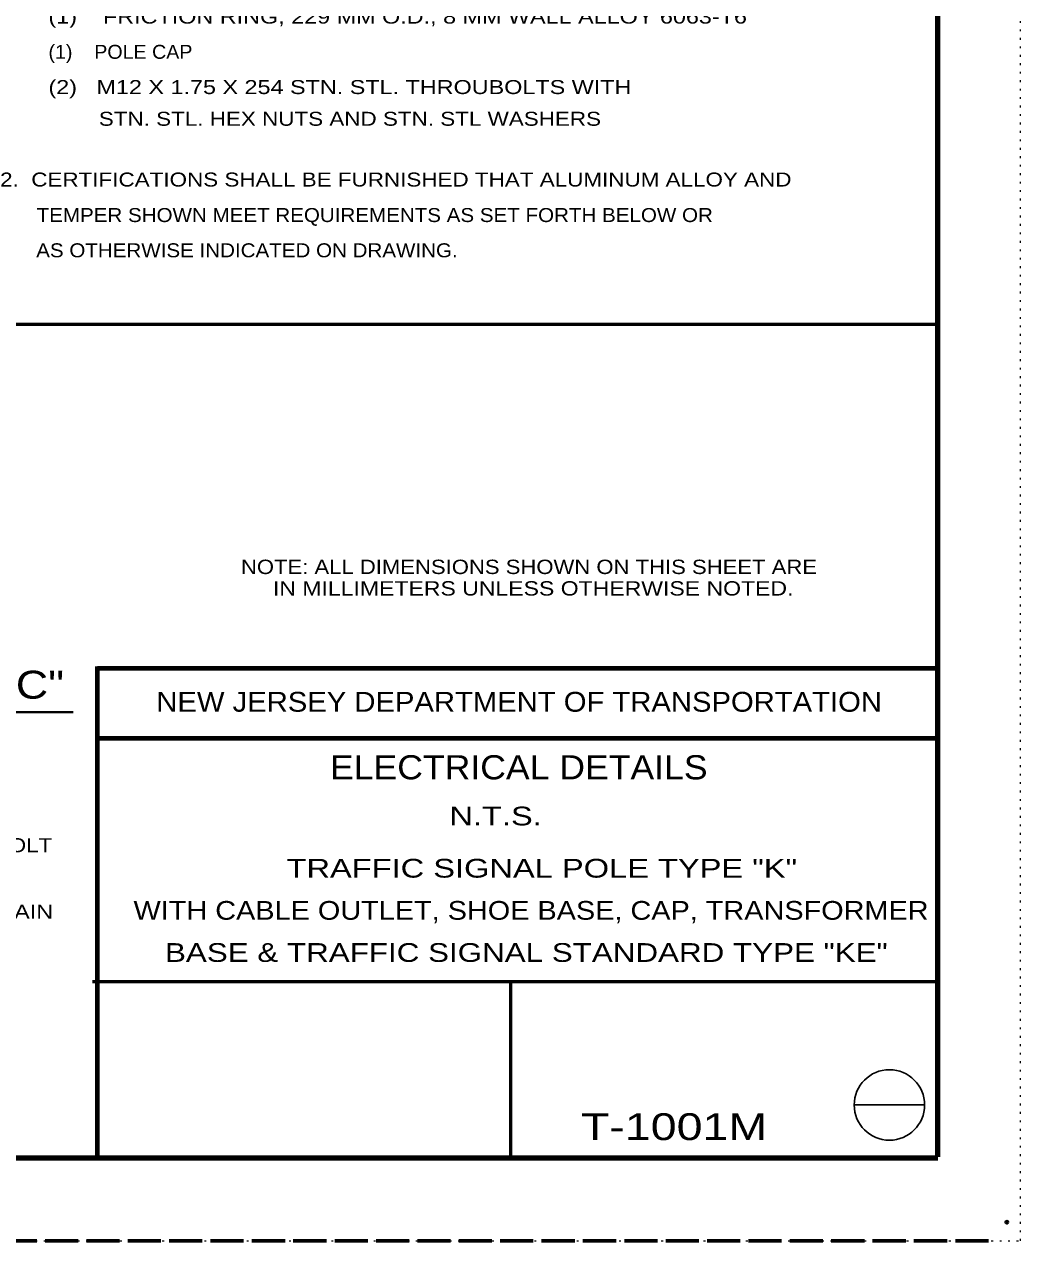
# Model space of a CAD drawing. Extents: x 312583 to 312854, y 144419 to 144597.
# Drawn here: x 312799.3 to 312853.5, y 144418.6 to 144484.7 of the extents above; entities that cross this region are included whole.
import ezdxf
from ezdxf.enums import TextEntityAlignment as Align

# ---------------------------------------------------------------- set-up
doc = ezdxf.new("R2010")
doc.units = 0
doc.header["$LTSCALE"] = 0.3
doc.header["$PDMODE"] = 32
doc.header["$PDSIZE"] = 0.15
doc.linetypes.add('DOTTED', pattern=[1.5, 0.3, -1.2])
doc.linetypes.add('LONG_DASHED', pattern=[7.5, 6, -1.5])
for name, color, linetype, lineweight in [('1', 7, 'Continuous', 40), ('10', 7, 'Continuous', 25), ('2', 7, 'Continuous', 13), ('62', 7, 'DOTTED', 13), ('63', 7, 'LONG_DASHED', 60)]:
    doc.layers.add(name, color=color, linetype=linetype, lineweight=lineweight)
doc.layers.add('5', color=7, linetype='Continuous')

msp = doc.modelspace()

# ---------------------------------------------------------------- linework, layer by layer
at = {"layer": '1', "lineweight": 158}
for p, q in [((312849, 144423.1446), (312849, 144585.0846)), ((312616.5, 144423.0846), (312849, 144423.0846))]:
    msp.add_line(p, q, dxfattribs=at)
at = {"layer": '1', "lineweight": 80}
for p, q in [((312803.31, 144423.1446), (312803.31, 144449.8146)), ((312803.31, 144449.7246), (312849, 144449.7246)), ((312803.31, 144445.9146), (312849, 144445.9146))]:
    msp.add_line(p, q, dxfattribs=at)
at = {"layer": '1', "lineweight": 53}
for p, q in [((312849, 144432.6666), (312803.0384, 144432.6666)), ((312825.7547, 144432.6666), (312825.7547, 144423.1446))]:
    msp.add_line(p, q, dxfattribs=at)
msp.add_lwpolyline([(312849, 144468.4167), (312795.5728, 144468.4167), (312795.5728, 144585.0846)], dxfattribs=at)
at = {"layer": '1'}
msp.add_point((312852.75, 144419.5846), dxfattribs=at)
at = {"layer": '10'}
msp.add_line((312844.4384, 144425.9659), (312848.2794, 144425.9659), dxfattribs=at)
msp.add_circle((312846.3635, 144425.9659), 1.9159, dxfattribs=at)
at = {"layer": '2', "lineweight": 40}
msp.add_line((312783.1061, 144447.3258), (312801.9889, 144447.3258), dxfattribs=at)
at = {"layer": '62'}
msp.add_lwpolyline([(312601.2, 144418.5846), (312853.5, 144418.5846), (312853.5, 144596.7846)], dxfattribs=at)
at = {"layer": '63'}
msp.add_line((312851.75, 144418.5846), (312583.526, 144418.5846), dxfattribs=at)

# ---------------------------------------------------------------- texts
at = {"layer": '1'}
for s, width, p in [('NOTE: ALL DIMENSIONS SHOWN ON THIS SHEET ARE', 1.15, (312811.1026, 144454.8446)), ('     IN MILLIMETERS UNLESS OTHERWISE NOTED.', 1.2, (312811.1025, 144453.6746))]:
    msp.add_text(s, height=0.78, dxfattribs=dict(at, width=width)).set_placement(p)
at = {"layer": '1', "width": 1.1}
for s, height, p in [('NEW JERSEY DEPARTMENT OF TRANSPORTATION', 1.08, (312826.2285, 144447.3546)), ('ELECTRICAL DETAILS', 1.315, (312826.2109, 144443.6759))]:
    msp.add_text(s, height=height, dxfattribs=at).set_placement(p, align=Align.CENTER)
at = {"layer": '2'}
for s, height, width, p in [('(1)    FRICTION RING, 229 MM O.D., 8 MM WALL ALLOY 6063-T6', 0.76, 1.25, (312800.6374, 144484.7846)), ('(1)    POLE CAP', 0.76, 1.05, (312800.6374, 144482.8679)), ('(2)   M12 X 1.75 X 254 STN. STL. THROUBOLTS WITH', 0.76, 1.25, (312800.6374, 144480.9513)), ('STN. STL. HEX NUTS AND STN. STL WASHERS', 0.76, 1.2, (312803.3744, 144479.2263)), ('2.  CERTIFICATIONS SHALL BE FURNISHED THAT ALUMINUM ALLOY AND', 0.76, 1.2, (312798.0077, 144475.9219)), ('TEMPER SHOWN MEET REQUIREMENTS AS SET FORTH BELOW OR', 0.76, 1.1, (312799.9934, 144473.9899)), ('AS OTHERWISE INDICATED ON DRAWING.', 0.76, 1.1, (312799.9704, 144472.0733)), ('SECTION  "C-C"', 1.52, 1.2, (312783.2242, 144448.0652)), ('STN. STL. HEX HEAD BOLT', 0.76, 1.2, (312785.0563, 144439.7139)), ('M24 DIA. STN. STL. PLAIN', 0.76, 1.25, (312785.2903, 144436.0971))]:
    msp.add_text(s, height=height, dxfattribs=dict(at, width=width)).set_placement(p)
for s, width, p in [('     N.T.S. ', 1.3, (312823.9633, 144441.1717)), ('        TRAFFIC SIGNAL POLE TYPE "K"        ', 1.3, (312827.4643, 144438.3322)), ('WITH CABLE OUTLET, SHOE BASE, CAP, TRANSFORMER', 1.15, (312826.8778, 144436.0399)), ('  BASE & TRAFFIC SIGNAL STANDARD TYPE "KE"  ', 1.25, (312826.621, 144433.7476))]:
    msp.add_text(s, height=1.02, dxfattribs=dict(at, width=width)).set_placement(p, align=Align.CENTER)
at = {"layer": '5', "width": 1.3}
msp.add_text('T-1001M  ', height=1.457, dxfattribs=at).set_placement((312835.3555, 144424.0569), align=Align.CENTER)

doc.saveas('drawing.dxf')
